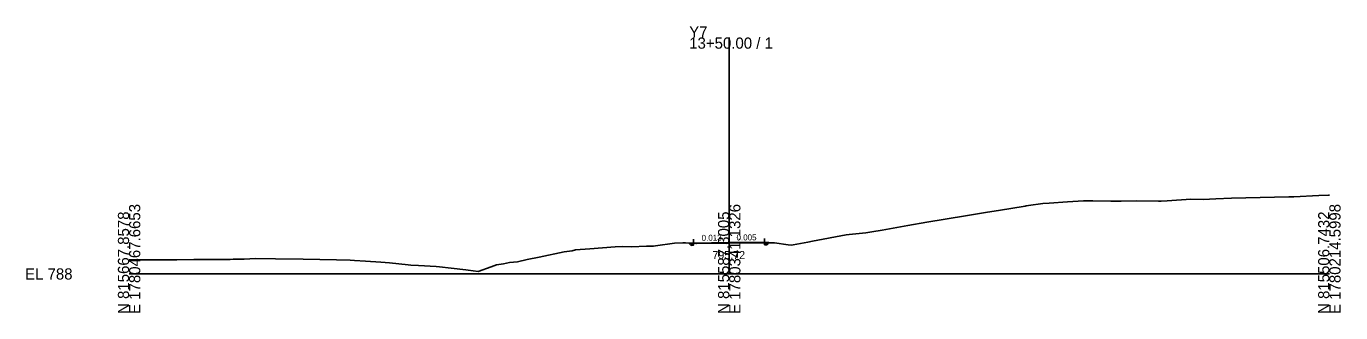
# Model space of a CAD drawing. Extents: x -26 to 2903, y -10 to 5536.
# Drawn here: x -25.7 to 302.8, y 3490.3 to 3561.9 of the extents above; entities that cross this region are included whole.
import ezdxf

# ---------------------------------------------------------------- set-up
doc = ezdxf.new("R2010")
doc.units = 0
for name, color, linetype in [('Exist Cross Section Cell', 7, 'Continuous'), ('Exist XS Center Line Elevation Label', 7, 'Continuous'), ('Exist XS Ground Line', 7, 'Continuous'), ('Prop XS Dump Level', 7, 'Continuous'), ('Prop XS Earthwork Shape', 7, 'Continuous'), ('Prop XS EOT Tick Mark', 7, 'Continuous'), ('Prop XS Finish Grade', 7, 'Continuous'), ('Prop XS Finish Grade Earthwork', 7, 'Continuous'), ('Prop XS Finish Grade Pavement', 7, 'Continuous'), ('Prop XS Pvmt Edge Slope', 7, 'Continuous'), ('Prop XS SE Text', 7, 'Continuous'), ('Prop XS Subgrade Earthwork', 7, 'Continuous')]:
    doc.layers.add(name, color=color, linetype=linetype)

msp = doc.modelspace()

# ---------------------------------------------------------------- linework, layer by layer
at = {"layer": 'Exist Cross Section Cell'}
for p, q in [((150, 3500), (150, 3559.1)), ((0, 3500), (150, 3500)), ((150, 3500), (300, 3500))]:
    msp.add_line(p, q, dxfattribs=at)
at = {"layer": 'Exist XS Ground Line'}
for p, q in [((259.47, 3518.26), (265.34, 3518.71)), ((265.34, 3518.71), (268.43, 3518.63)), ((268.43, 3518.63), (271.66, 3518.75)), ((271.66, 3518.75), (275.51, 3518.92)), ((275.51, 3518.92), (289.85, 3519.26)), ((289.85, 3519.26), (290.56, 3519.28)), ((290.56, 3519.28), (291.16, 3519.31)), ((291.16, 3519.31), (297.39, 3519.64)), ((297.39, 3519.64), (299.76, 3519.69)), ((299.76, 3519.69), (300, 3519.7)), ((209.06, 3514.51), (214.57, 3515.47)), ((214.57, 3515.47), (217.34, 3515.86)), ((217.34, 3515.86), (223.94, 3516.98)), ((223.94, 3516.98), (224.26, 3517.04)), ((224.26, 3517.04), (224.84, 3517.12)), ((224.84, 3517.12), (228.42, 3517.6)), ((228.42, 3517.6), (229.94, 3517.73)), ((229.94, 3517.73), (234.54, 3518.02)), ((234.54, 3518.02), (238.54, 3518.26)), ((238.54, 3518.26), (239.85, 3518.3)), ((239.85, 3518.3), (240.87, 3518.29)), ((240.87, 3518.29), (245.4, 3518.22)), ((245.4, 3518.22), (248, 3518.18)), ((248, 3518.18), (251.81, 3518.24)), ((251.81, 3518.24), (257.33, 3518.22)), ((257.33, 3518.22), (258, 3518.22)), ((258, 3518.22), (259.47, 3518.26)), ((188.19, 3510.93), (194.67, 3512.09)), ((194.67, 3512.09), (199.37, 3512.92)), ((199.37, 3512.92), (209.06, 3514.51)), ((170.81, 3508.19), (179.21, 3509.75)), ((179.21, 3509.75), (179.97, 3509.84)), ((179.97, 3509.84), (184.12, 3510.3)), ((184.12, 3510.3), (185.61, 3510.51)), ((185.61, 3510.51), (188.19, 3510.93)), ((102.51, 3504.21), (108.76, 3505.5)), ((108.76, 3505.5), (110.72, 3505.81)), ((110.72, 3505.81), (111.62, 3505.99)), ((111.62, 3505.99), (115.13, 3506.26)), ((115.13, 3506.26), (121.53, 3506.76)), ((121.53, 3506.76), (123.37, 3506.84)), ((123.37, 3506.84), (125.61, 3506.78)), ((125.61, 3506.78), (129.32, 3506.91)), ((129.32, 3506.91), (130.62, 3506.98)), ((130.62, 3506.98), (131.05, 3506.98)), ((131.05, 3506.98), (131.55, 3507.05)), ((131.55, 3507.05), (136.36, 3507.69)), ((136.36, 3507.69), (138.43, 3507.74)), ((138.43, 3507.74), (139.06, 3507.74)), ((139.06, 3507.74), (141.04, 3507.61)), ((141.04, 3507.61), (146.76, 3507.68)), ((146.76, 3507.68), (149.96, 3507.72)), ((149.96, 3507.72), (157.68, 3507.76)), ((157.68, 3507.76), (158.84, 3507.78)), ((158.84, 3507.78), (159.23, 3507.79)), ((159.23, 3507.79), (161.34, 3507.74)), ((161.34, 3507.74), (164.77, 3507.26)), ((164.77, 3507.26), (165.46, 3507.18)), ((165.46, 3507.18), (165.99, 3507.28)), ((165.99, 3507.28), (169.68, 3507.96)), ((169.68, 3507.96), (170.81, 3508.19)), ((0, 3503.53), (5.07, 3503.54)), ((5.07, 3503.54), (11.95, 3503.55)), ((11.95, 3503.55), (16.2, 3503.58)), ((16.2, 3503.58), (17.45, 3503.59)), ((17.45, 3503.59), (18.53, 3503.61)), ((18.53, 3503.61), (19.6, 3503.61)), ((19.6, 3503.61), (20.85, 3503.62)), ((20.85, 3503.62), (21.25, 3503.62)), ((21.25, 3503.62), (21.7, 3503.63)), ((21.7, 3503.63), (22.79, 3503.63)), ((22.79, 3503.63), (24.37, 3503.63)), ((24.37, 3503.63), (25.29, 3503.64)), ((25.29, 3503.64), (26.03, 3503.65)), ((26.03, 3503.65), (26.64, 3503.66)), ((26.64, 3503.66), (27.14, 3503.67)), ((27.14, 3503.67), (27.59, 3503.68)), ((27.59, 3503.68), (28.04, 3503.69)), ((28.04, 3503.69), (28.43, 3503.7)), ((28.43, 3503.7), (28.78, 3503.71)), ((28.78, 3503.71), (31.56, 3503.82)), ((31.56, 3503.82), (36.59, 3503.77)), ((36.59, 3503.77), (43.51, 3503.69)), ((43.51, 3503.69), (51.83, 3503.49)), ((51.83, 3503.49), (55.23, 3503.4)), ((55.23, 3503.4), (56.36, 3503.34)), ((56.36, 3503.34), (59.1, 3503.2)), ((59.1, 3503.2), (62.93, 3502.91)), ((62.93, 3502.91), (65.07, 3502.78)), ((65.07, 3502.78), (69.78, 3502.3)), ((69.78, 3502.3), (70.45, 3502.23)), ((70.45, 3502.23), (72.33, 3502.13)), ((90.53, 3501.76), (91.84, 3502.25)), ((91.84, 3502.25), (93.59, 3502.52)), ((93.59, 3502.52), (95.12, 3502.83)), ((95.12, 3502.83), (97.05, 3503.06)), ((97.05, 3503.06), (99.52, 3503.57)), ((99.52, 3503.57), (102.51, 3504.21)), ((72.33, 3502.13), (76.76, 3501.88)), ((76.76, 3501.88), (77.62, 3501.79)), ((77.62, 3501.79), (80.51, 3501.48)), ((80.51, 3501.48), (84.19, 3501.05)), ((84.19, 3501.05), (84.76, 3500.95)), ((84.76, 3500.95), (87.22, 3500.64)), ((87.22, 3500.64), (90.53, 3501.76))]:
    msp.add_line(p, q, dxfattribs=at)
at = {"layer": 'Prop XS Dump Level'}
for p, q in [((141.04, 3507.73), (150, 3507.85)), ((141.04, 3507.73), (150, 3507.85)), ((150, 3507.85), (158.84, 3507.89)), ((150, 3507.85), (158.84, 3507.89))]:
    msp.add_line(p, q, dxfattribs=at)
at = {"layer": 'Prop XS Earthwork Shape'}
for points in [[(139.94, 3507.65), (139.06, 3507.74), (141.04, 3507.61), (141.04, 3507.15), (140.45, 3507.14)], [(159.42, 3507.31), (159.88, 3507.78), (159.23, 3507.79), (158.84, 3507.78), (158.84, 3507.31)], [(159.88, 3507.78), (161.34, 3507.74), (159.94, 3507.83)]]:
    msp.add_lwpolyline(points, close=True, dxfattribs=at)
at = {"layer": 'Prop XS EOT Tick Mark'}
for p, q in [((141.04, 3507.73), (141.04, 3508.73)), ((141.04, 3507.73), (141.04, 3508.73)), ((158.84, 3507.89), (158.84, 3508.89)), ((158.84, 3507.89), (158.84, 3508.89))]:
    msp.add_line(p, q, dxfattribs=at)
at = {"layer": 'Prop XS Finish Grade'}
for p, q in [((141.04, 3507.73), (139.94, 3507.65)), ((158.84, 3507.89), (159.94, 3507.83))]:
    msp.add_line(p, q, dxfattribs=at)
at = {"layer": 'Prop XS Finish Grade Earthwork'}
for p, q in [((139.94, 3507.65), (139.06, 3507.74)), ((159.94, 3507.83), (161.34, 3507.74))]:
    msp.add_line(p, q, dxfattribs=at)
at = {"layer": 'Prop XS Finish Grade Pavement'}
for p, q in [((141.04, 3507.73), (150, 3507.85)), ((141.04, 3507.73), (150, 3507.85)), ((150, 3507.85), (158.84, 3507.89)), ((150, 3507.85), (158.84, 3507.89))]:
    msp.add_line(p, q, dxfattribs=at)
at = {"layer": 'Prop XS Pvmt Edge Slope'}
for p, q in [((141.04, 3507.73), (140.45, 3507.14)), ((141.04, 3507.73), (140.49, 3507.19)), ((158.84, 3507.89), (159.42, 3507.31)), ((158.84, 3507.89), (159.38, 3507.36))]:
    msp.add_line(p, q, dxfattribs=at)
at = {"layer": 'Prop XS Subgrade Earthwork'}
for p, q in [((140.45, 3507.14), (139.94, 3507.65)), ((140.45, 3507.14), (141.04, 3507.15)), ((141.04, 3507.15), (141.04, 3507.61)), ((158.84, 3507.31), (158.84, 3507.78)), ((158.84, 3507.31), (159.42, 3507.31)), ((159.42, 3507.31), (159.94, 3507.83))]:
    msp.add_line(p, q, dxfattribs=at)

# ---------------------------------------------------------------- texts
at = {"layer": 'Exist Cross Section Cell'}
for s, p in [('Y7', (140, 3559.1)), ('13+50.00 / 1', (140, 3556.3)), ('EL 788', (-26, 3498.6))]:
    msp.add_text(s, height=2.8, dxfattribs=at).set_placement(p)
for s, p in [('N 815667.8578', (0, 3490)), ('E 1780467.6653', (2.8, 3490)), ('N 815587.3005', (150, 3490)), ('E 1780341.1326', (152.8, 3490)), ('N 815506.7432', (300, 3490)), ('E 1780214.5998', (302.8, 3490))]:
    msp.add_text(s, height=2.8, rotation=90, dxfattribs=at).set_placement(p)
at = {"layer": 'Exist XS Center Line Elevation Label'}
msp.add_text('795.72', height=2, dxfattribs=at).set_placement((145.79, 3503.72))
at = {"layer": 'Prop XS Dump Level'}
for s, height, p in [('Eop', 0.3, (141.04, 3507.31)), ('Eop', 0.3, (141.04, 3507.31)), ('Eop', 0.3, (158.84, 3507.48)), ('Eop', 0.3, (158.84, 3507.48)), ('Case1', 0.04, (162.84, 3507.64))]:
    msp.add_text(s, height=height, dxfattribs=at).set_placement(p)
at = {"layer": 'Prop XS SE Text'}
for s, rotation, p in [('0.013', 0.7276, (143.11, 3508.26)), ('0.013', 0.7276, (143.11, 3508.26)), ('0.005', 0.3037, (151.82, 3508.36)), ('0.005', 0.3037, (151.82, 3508.36))]:
    msp.add_text(s, height=1.5, rotation=rotation, dxfattribs=at).set_placement(p)

doc.saveas('drawing.dxf')
